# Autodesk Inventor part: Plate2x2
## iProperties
Created: 2006-02
Part Number: Plate2x2
Material: Stainless Steel
Document SubType Name: Modeling
Designer: 40664
Mass: 200889 g
Surface Area: 50370 cm^2
Volume: 24862.5 cm^3
Density: 8.08 g/cm^3
CSToolsMass: 201.0
CSToolsVolume: 24862500.0
CSToolsArea: 50370.0
Author: 40664
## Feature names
1. Extrusion2
